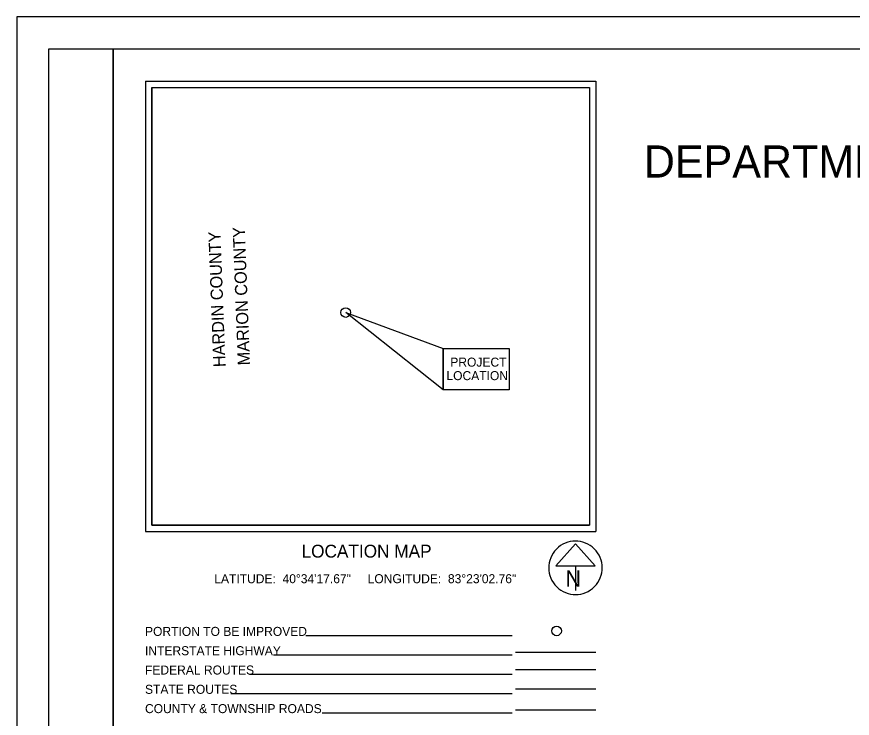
# Model space of a CAD drawing. Extents: x 0 to 34, y 0 to 22.
# Drawn here: x 0 to 12.99, y 11.1 to 22 of the extents above; entities that cross this region are included whole.
import ezdxf

# ---------------------------------------------------------------- set-up
doc = ezdxf.new("R2010")
doc.units = 0
for name, color, linetype in [('GM_X_County', 7, 'Continuous'), ('GM_X_County_Road_Text', 7, 'Continuous'), ('GM_X_Minor_Lake', 7, 'Continuous'), ('GM_X_Minor_Lake_Text', 7, 'Continuous'), ('GM_X_Minor_River', 7, 'Continuous'), ('GM_X_Minor_River_Text', 7, 'Continuous')]:
    doc.layers.add(name, color=color, linetype=linetype)

msp = doc.modelspace()

# ---------------------------------------------------------------- linework, layer by layer
at = {"layer": 'GM_X_County'}
msp.add_lwpolyline([(0, 0), (34, 0), (34, 22), (0, 22)], close=True, dxfattribs=at)
at = {"layer": 'GM_X_County_Road_Text'}
for points in [[(6.628, 16.2), (5.114, 17.403), (6.628, 16.846)], [(6.628, 16.846), (7.652, 16.846), (7.652, 16.2), (6.628, 16.2)], [(6.628, 16.846), (7.652, 16.846), (7.652, 16.2), (6.628, 16.2)]]:
    msp.add_lwpolyline(points, close=True, dxfattribs=at)
for centre in [(5.114, 17.403), (8.391, 12.455)]:
    msp.add_circle(centre, 0.075, dxfattribs=at)
at = {"layer": 'GM_X_Minor_Lake_Text'}
for p, q in [((2, 21), (9, 21)), ((2, 21), (2, 14)), ((9, 21), (9, 14)), ((2.1, 20.9), (2.1, 14.1)), ((2.1, 20.9), (8.9, 20.9)), ((8.9, 20.9), (8.9, 14.1)), ((2.1, 14.1), (2.1, 14.1)), ((2.1, 14.1), (8.9, 14.1)), ((2.1, 14.1), (2.1, 14.1)), ((2, 14), (9, 14)), ((8.685, 13.809), (8.377, 13.468)), ((8.992, 13.468), (8.685, 13.809)), ((8.377, 13.468), (8.992, 13.468)), ((8.685, 13.468), (8.685, 13.081)), ((8.685, 13.435), (8.685, 13.435)), ((8.685, 13.435), (8.685, 13.435)), ((7.7, 12.377), (4.494, 12.377)), ((9, 12.121), (7.75, 12.121)), ((7.7, 12.077), (3.99, 12.077)), ((9, 11.849), (7.75, 11.849)), ((7.7, 11.777), (3.619, 11.777)), ((7.7, 11.477), (3.329, 11.477)), ((9, 11.549), (7.75, 11.549)), ((7.7, 11.177), (4.745, 11.177)), ((9, 11.222), (7.75, 11.222))]:
    msp.add_line(p, q, dxfattribs=at)
msp.add_arc((8.685, 13.435), 0.415, 129.7798, 129.7633, dxfattribs=at)
at = {"layer": 'GM_X_Minor_River'}
msp.add_lwpolyline([(2.1, 20.9), (8.9, 20.9), (8.9, 14.1), (2.1, 14.1)], close=True, dxfattribs=at)
at = {"layer": 'GM_X_Minor_River_Text'}
for points in [[(0.5, 21.5), (1.5, 21.5), (1.5, 0.5), (0.5, 0.5)], [(1.5, 21.5), (33.5, 21.5), (33.5, 0.5), (1.5, 0.5)]]:
    msp.add_lwpolyline(points, close=True, dxfattribs=at)

# ---------------------------------------------------------------- texts
at = {"layer": 'GM_X_County_Road_Text'}
for s, p in [('MARION COUNTY', (3.627, 16.585)), ('HARDIN COUNTY', (3.247, 16.557))]:
    msp.add_text(s, height=0.18939, rotation=92.1888, dxfattribs=at).set_placement(p)
for s, p in [('PROJECT', (6.739, 16.562)), ('LOCATION', (6.679, 16.352))]:
    msp.add_text(s, height=0.14, dxfattribs=at).set_placement(p)
at = {"layer": 'GM_X_Minor_Lake'}
for s, height, p in [('DEPARTMENT OF TRANSPORTATION', 0.5, (9.747, 19.5)), ('LOCATION MAP', 0.2, (4.427, 13.594)), ('LATITUDE:  40°34\'17.67"     LONGITUDE:  83°23\'02.76"', 0.14, (3.071, 13.196)), ('PORTION TO BE IMPROVED', 0.14, (1.994, 12.377)), ('INTERSTATE HIGHWAY', 0.14, (1.994, 12.077)), ('FEDERAL ROUTES', 0.14, (1.994, 11.777)), ('STATE ROUTES', 0.14, (1.994, 11.477)), ('COUNTY & TOWNSHIP ROADS', 0.14, (1.994, 11.177))]:
    msp.add_text(s, height=height, dxfattribs=at).set_placement(p)
at = {"layer": 'GM_X_Minor_Lake_Text'}
msp.add_text('N', height=0.25, dxfattribs=at).set_placement((8.529, 13.144))

doc.saveas('drawing.dxf')
